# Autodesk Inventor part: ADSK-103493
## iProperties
Shininess: 20.0
Created: 2001-03
Part Number: ADSK-103493
Document SubType Name: Modeling
Designer: Administrator
Stock Number: ADSK-103493
Density: 1 g/cm^3
Density: 0.0
Volumn: 0.0
Area: 0.0
PropertySet Name: Model Information
Control State: 0
Master: False
Checked Out: False
Author: Administrator
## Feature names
1. Extrusion1
2. Shell1
3. Extrusion2
4. Extrusion5
5. Extrusion6
6. Extrusion7
7. Hole1
8. Extrusion8
9. Extrusion9
